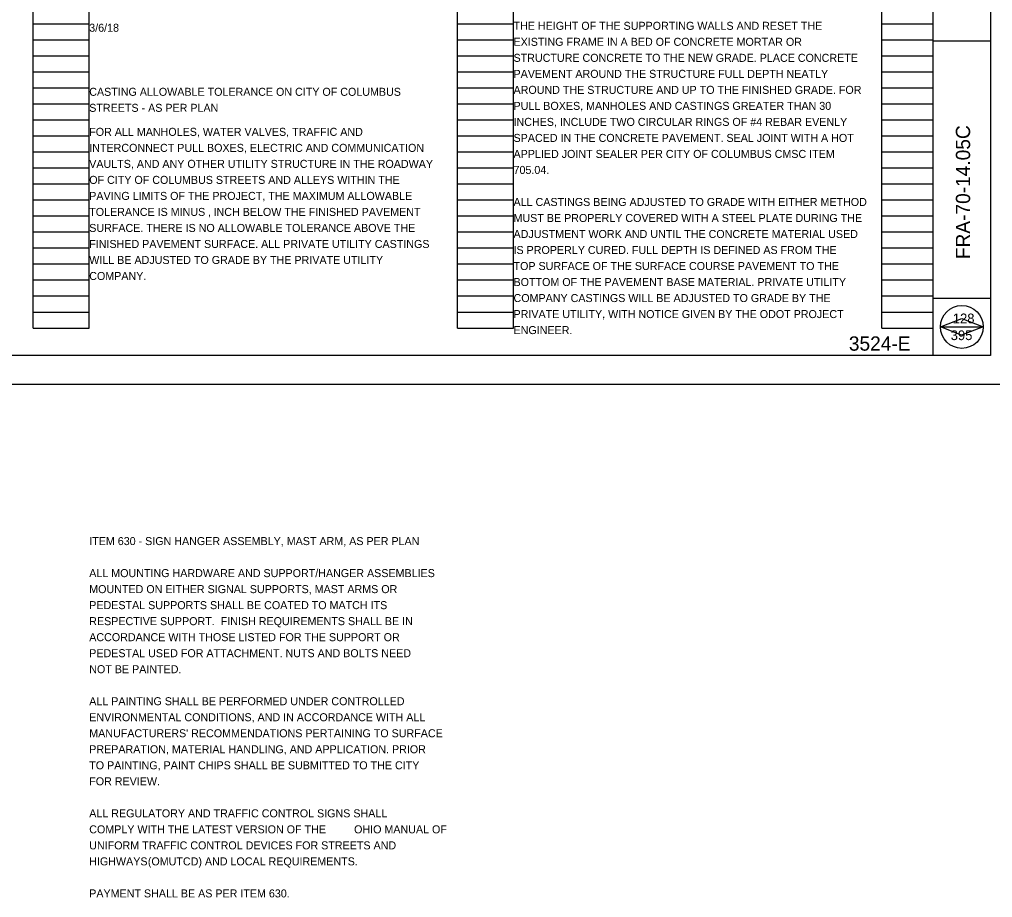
# Model space of a CAD drawing. Extents: x -62 to 50, y -16 to 14.
# Drawn here: x 16.01 to 33.03, y -16.49 to -1.13 of the extents above; entities that cross this region are included whole.
import ezdxf

# ---------------------------------------------------------------- set-up
doc = ezdxf.new("R2010")
doc.units = 0
for name, color, linetype in [('Level 63', 7, 'Continuous'), ('PF_P_Text', 7, 'Continuous'), ('SC_Scratch1', 7, 'Continuous'), ('SH_Cut_Line', 7, 'Continuous'), ('SH_Data', 7, 'Continuous'), ('SH_Text', 7, 'Continuous')]:
    doc.layers.add(name, color=color, linetype=linetype)

msp = doc.modelspace()

# ---------------------------------------------------------------- linework, layer by layer
at = {"layer": 'Level 63'}
msp.add_line((32.119, -6.508), (32.869, -6.508), dxfattribs=at)
msp.add_circle((32.494, -6.508), 0.375, dxfattribs=at)
at = {"layer": 'PF_P_Text'}
for p, q in [((31.994, -7.008), (31.994, 13.992)), ((31.994, -1.508), (32.994, -1.508)), ((31.994, -6.008), (32.994, -6.008))]:
    msp.add_line(p, q, dxfattribs=at)
msp.add_lwpolyline([(1.494, 13.992), (32.994, 13.992), (32.994, -7.008), (1.494, -7.008)], close=True, dxfattribs=at)
at = {"layer": 'SC_Scratch1'}
for p, q in [((16.254, -6.528), (16.254, 13.632)), ((17.234, -6.528), (17.234, 13.632)), ((23.674, -6.528), (23.674, 13.632)), ((24.654, -6.528), (24.654, 13.632)), ((31.094, -6.528), (31.094, 13.632)), ((31.994, -6.528), (31.994, 13.632)), ((16.254, -1.208), (17.234, -1.208)), ((23.674, -1.208), (24.654, -1.208)), ((31.094, -1.208), (31.994, -1.208)), ((16.254, -1.488), (17.234, -1.488)), ((23.674, -1.488), (24.654, -1.488)), ((31.094, -1.488), (31.994, -1.488)), ((16.254, -1.768), (17.234, -1.768)), ((23.674, -1.768), (24.654, -1.768)), ((31.094, -1.768), (31.994, -1.768)), ((16.254, -2.048), (17.234, -2.048)), ((23.674, -2.048), (24.654, -2.048)), ((31.094, -2.048), (31.994, -2.048)), ((16.254, -2.328), (17.234, -2.328)), ((23.674, -2.328), (24.654, -2.328)), ((31.094, -2.328), (31.994, -2.328)), ((16.254, -2.608), (17.234, -2.608)), ((23.674, -2.608), (24.654, -2.608)), ((31.094, -2.608), (31.994, -2.608)), ((16.254, -2.888), (17.234, -2.888)), ((23.674, -2.888), (24.654, -2.888)), ((31.094, -2.888), (31.994, -2.888)), ((16.254, -3.168), (17.234, -3.168)), ((23.674, -3.168), (24.654, -3.168)), ((31.094, -3.168), (31.994, -3.168)), ((16.254, -3.448), (17.234, -3.448)), ((23.674, -3.448), (24.654, -3.448)), ((31.094, -3.448), (31.994, -3.448)), ((16.254, -3.728), (17.234, -3.728)), ((23.674, -3.728), (24.654, -3.728)), ((31.094, -3.728), (31.994, -3.728)), ((16.254, -4.008), (17.234, -4.008)), ((23.674, -4.008), (24.654, -4.008)), ((31.094, -4.008), (31.994, -4.008)), ((16.254, -4.288), (17.234, -4.288)), ((23.674, -4.288), (24.654, -4.288)), ((31.094, -4.288), (31.994, -4.288)), ((16.254, -4.568), (17.234, -4.568)), ((23.674, -4.568), (24.654, -4.568)), ((31.094, -4.568), (31.994, -4.568)), ((16.254, -4.848), (17.234, -4.848)), ((23.674, -4.848), (24.654, -4.848)), ((31.094, -4.848), (31.994, -4.848)), ((16.254, -5.128), (17.234, -5.128)), ((23.674, -5.128), (24.654, -5.128)), ((31.094, -5.128), (31.994, -5.128)), ((16.254, -5.408), (17.234, -5.408)), ((23.674, -5.408), (24.654, -5.408)), ((31.094, -5.408), (31.994, -5.408)), ((16.254, -5.688), (17.234, -5.688)), ((23.674, -5.688), (24.654, -5.688)), ((31.094, -5.688), (31.994, -5.688)), ((16.254, -5.968), (17.234, -5.968)), ((23.674, -5.968), (24.654, -5.968)), ((31.094, -5.968), (31.994, -5.968)), ((16.254, -6.248), (17.234, -6.248)), ((23.674, -6.248), (24.654, -6.248)), ((31.094, -6.248), (31.994, -6.248)), ((32.119, -6.508), (32.495, -6.36)), ((32.495, -6.36), (32.869, -6.508)), ((16.254, -6.528), (17.234, -6.528)), ((23.674, -6.528), (24.654, -6.528)), ((31.094, -6.528), (31.994, -6.528)), ((32.49, -6.654), (32.119, -6.508)), ((32.869, -6.508), (32.49, -6.654))]:
    msp.add_line(p, q, dxfattribs=at)
at = {"layer": 'SH_Cut_Line'}
msp.add_lwpolyline([(-0.506, -7.508), (33.494, -7.508), (33.494, 14.492), (-0.506, 14.492)], close=True, dxfattribs=at)

# ---------------------------------------------------------------- texts
at = {"layer": 'Level 63'}
msp.add_text('FRA-70-14.05C', height=0.25, rotation=90, dxfattribs=at).set_placement((32.639, -5.324))
at = {"layer": 'SH_Data'}
msp.add_text('3524-E', height=0.25, rotation=359.9999, dxfattribs=at).set_placement((30.518, -6.924))
at = {"layer": 'SH_Text'}
for s, height, p in [('THE HEIGHT OF THE SUPPORTING WALLS AND RESET THE ', 0.14, (24.654, -1.314)), ('3/6/18', 0.14, (17.234, -1.348)), ('EXISTING FRAME IN A BED OF CONCRETE MORTAR OR ', 0.14, (24.654, -1.594)), ('STRUCTURE CONCRETE TO THE NEW GRADE. PLACE CONCRETE ', 0.14, (24.654, -1.874)), ('PAVEMENT AROUND THE STRUCTURE FULL DEPTH NEATLY ', 0.14, (24.654, -2.154)), ('CASTING ALLOWABLE TOLERANCE ON CITY OF COLUMBUS ', 0.14, (17.234, -2.468)), ('AROUND THE STRUCTURE AND UP TO THE FINISHED GRADE. FOR ', 0.14, (24.654, -2.434)), ('STREETS - AS PER PLAN', 0.14, (17.234, -2.748)), ('PULL BOXES, MANHOLES AND CASTINGS GREATER THAN 30 ', 0.14, (24.654, -2.714)), ('INCHES, INCLUDE TWO CIRCULAR RINGS OF #4 REBAR EVENLY ', 0.14, (24.654, -2.994)), ('FOR ALL MANHOLES, WATER VALVES, TRAFFIC AND ', 0.14, (17.234, -3.168)), ('SPACED IN THE CONCRETE PAVEMENT. SEAL JOINT WITH A HOT ', 0.14, (24.654, -3.274)), ('INTERCONNECT PULL BOXES, ELECTRIC AND COMMUNICATION ', 0.14, (17.234, -3.448)), ('APPLIED JOINT SEALER PER CITY OF COLUMBUS CMSC ITEM ', 0.14, (24.654, -3.554)), ('VAULTS, AND ANY OTHER UTILITY STRUCTURE IN THE ROADWAY ', 0.14, (17.234, -3.728)), ('705.04.', 0.14, (24.654, -3.834)), ('OF CITY OF COLUMBUS STREETS AND ALLEYS WITHIN THE ', 0.14, (17.234, -4.008)), ('PAVING LIMITS OF THE PROJECT, THE MAXIMUM ALLOWABLE ', 0.14, (17.234, -4.288)), ('ALL CASTINGS BEING ADJUSTED TO GRADE WITH EITHER METHOD ', 0.14, (24.654, -4.394)), ('TOLERANCE IS MINUS ‚ INCH BELOW THE FINISHED PAVEMENT ', 0.14, (17.234, -4.568)), ('MUST BE PROPERLY COVERED WITH A STEEL PLATE DURING THE ', 0.14, (24.654, -4.674)), ('SURFACE. THERE IS NO ALLOWABLE TOLERANCE ABOVE THE ', 0.14, (17.234, -4.848)), ('ADJUSTMENT WORK AND UNTIL THE CONCRETE MATERIAL USED ', 0.14, (24.654, -4.954)), ('FINISHED PAVEMENT SURFACE. ALL PRIVATE UTILITY CASTINGS ', 0.14, (17.234, -5.128)), ('IS PROPERLY CURED. FULL DEPTH IS DEFINED AS FROM THE ', 0.14, (24.654, -5.234)), ('WILL BE ADJUSTED TO GRADE BY THE PRIVATE UTILITY ', 0.14, (17.234, -5.408)), ('TOP SURFACE OF THE SURFACE COURSE PAVEMENT TO THE ', 0.14, (24.654, -5.514)), ('COMPANY.', 0.14, (17.234, -5.688)), ('BOTTOM OF THE PAVEMENT BASE MATERIAL. PRIVATE UTILITY ', 0.14, (24.654, -5.794)), ('COMPANY CASTINGS WILL BE ADJUSTED TO GRADE BY THE ', 0.14, (24.654, -6.074)), ('PRIVATE UTILITY, WITH NOTICE GIVEN BY THE ODOT PROJECT ', 0.14, (24.654, -6.354)), ('128', 0.17, (32.336, -6.445)), ('ENGINEER. ', 0.14, (24.654, -6.634)), ('395', 0.17, (32.299, -6.739)), ('ITEM 630 - SIGN HANGER ASSEMBLY, MAST ARM, AS PER PLAN', 0.14, (17.234, -10.323)), ('ALL MOUNTING HARDWARE AND SUPPORT/HANGER ASSEMBLIES ', 0.14, (17.234, -10.883)), ('MOUNTED ON EITHER SIGNAL SUPPORTS, MAST ARMS OR ', 0.14, (17.234, -11.163)), ('PEDESTAL SUPPORTS SHALL BE COATED TO MATCH ITS ', 0.14, (17.234, -11.443)), ('RESPECTIVE SUPPORT.  FINISH REQUIREMENTS SHALL BE IN ', 0.14, (17.234, -11.723)), ('ACCORDANCE WITH THOSE LISTED FOR THE SUPPORT OR ', 0.14, (17.234, -12.003)), ('PEDESTAL USED FOR ATTACHMENT. NUTS AND BOLTS NEED ', 0.14, (17.234, -12.283)), ('NOT BE PAINTED.', 0.14, (17.234, -12.563)), ('ALL PAINTING SHALL BE PERFORMED UNDER CONTROLLED ', 0.14, (17.234, -13.123)), ('ENVIRONMENTAL CONDITIONS, AND IN ACCORDANCE WITH ALL ', 0.14, (17.234, -13.403)), ("MANUFACTURERS' RECOMMENDATIONS PERTAINING TO SURFACE ", 0.14, (17.234, -13.683)), ('PREPARATION, MATERIAL HANDLING, AND APPLICATION. PRIOR ', 0.14, (17.234, -13.963)), ('TO PAINTING, PAINT CHIPS SHALL BE SUBMITTED TO THE CITY ', 0.14, (17.234, -14.243)), ('FOR REVIEW.', 0.14, (17.234, -14.523)), ('ALL REGULATORY AND TRAFFIC CONTROL SIGNS SHALL ', 0.14, (17.234, -15.083)), ('COMPLY WITH THE LATEST VERSION OF THE ', 0.14, (17.234, -15.363)), ('OHIO MANUAL OF ', 0.14, (21.866, -15.363)), ('UNIFORM TRAFFIC CONTROL DEVICES FOR STREETS AND ', 0.14, (17.234, -15.643)), ('HIGHWAYS', 0.14, (17.234, -15.923)), (' (OMUTCD) AND LOCAL REQUIREMENTS.', 0.14, (18.207, -15.923)), ('PAYMENT SHALL BE AS PER ITEM 630.', 0.14, (17.234, -16.483))]:
    msp.add_text(s, height=height, dxfattribs=at).set_placement(p)

doc.saveas('drawing.dxf')
